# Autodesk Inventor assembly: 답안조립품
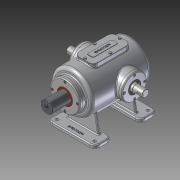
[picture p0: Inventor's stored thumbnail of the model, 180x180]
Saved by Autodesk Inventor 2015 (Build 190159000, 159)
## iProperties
Created: 2016-02
Part Number: 답안조립품
Document SubType Name: Assembly
Designer: Administrator
Mass: 8191.31 g
Surface Area: 4241.85 cm^2
Volume: 1855.5 cm^3
Density: 4.4146 g/cm^3
Author: Administrator
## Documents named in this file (15)
- C:\Users\Administrator\Desktop\360220V1014\답안조립품.iam
- C:\Users\Administrator\Desktop\360220V1014\본체.ipt
- C:\Users\Administrator\Desktop\360220V1014\상부커버.ipt
- C:\Users\Administrator\Desktop\360220V1014\육각머리볼트 M4.ipt
- C:\Users\Administrator\Desktop\360220V1014\슬라이드 커버.ipt
- C:\Users\Administrator\Desktop\360220V1014\볼트 M4x0.7.ipt
- C:\Users\Administrator\Desktop\360220V1014\축 커버.ipt
- C:\Users\Administrator\Desktop\360220V1014\오일실.ipt
- 오일실.ipt
- C:\Users\Administrator\Desktop\360220V1014\베어링 6205.ipt
- 베어링 6205.ipt
- C:\Users\Administrator\Desktop\360220V1014\편심축.ipt
- C:\Users\Administrator\Desktop\360220V1014\부시.ipt
- C:\Users\Administrator\Desktop\360220V1014\가변스프링.ipt
- C:\Users\Administrator\Desktop\360220V1014\슬라이드.ipt
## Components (13 placed, 2 different names)
1. 가변스프링:1
2. M4x0.7:1
3. M4x0.7:2
4. M4x0.7:3
5. M4x0.7:4
6. M4x0.7:5
7. M4x0.7:7
8. M4x0.7:8
9. M4x0.7:9
10. M4x0.7:6
11. M4x0.7:10
12. M4x0.7:11
13. M4x0.7:12
